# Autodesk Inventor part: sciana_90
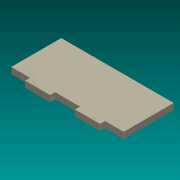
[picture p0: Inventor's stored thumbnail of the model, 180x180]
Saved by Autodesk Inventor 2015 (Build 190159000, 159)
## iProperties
Created: 2016-02
Part Number: sciana_90
Material: Generic
Document SubType Name: Modeling
Designer: Rafał
Density: 1 g/cm^3
Appearance: Light Beige
Author: Rafał
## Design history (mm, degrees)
sketch "Sketch1"
  geometry: L1 (0, 0)-(-90, 0); L2 (-90, 0)-(-90, 40); L3 (-90, 40)-(0, 40); L4 (0, 40)-(0, 0); L5 (-15, 0)-(-35, 0); L6 (-35, 0)-(-35, -4); L7 (-35, -4)-(-15, -4); L8 (-15, -4)-(-15, 0); L9 (-75, 0)-(-55, 0); L10 (-55, 0)-(-55, -4); L11 (-55, -4)-(-75, -4); L12 (-75, -4)-(-75, 0)
  constraints: 24 end point, 6 parallel, 3 horizontal, 3 perpendicular, 2 point on line
  dimensions: "d0" = 90 distance of L2.end L3.end; "d1" = 40 distance of L1.end L2.end; "d2" = 20 distance of L7.end L6.end; "d3" = 4 distance of L6.end L5.end; "d4" = 15 distance between parallel lines of L4 L8; "d5" = 20 distance of L10.end L11.end; "d6" = 15 distance between parallel lines of L12 L2
extrude "Extrusion1" new body sketch "Sketch1" distance "d7" = 5; taper "d8" = 0 deg
body "Solid1"
